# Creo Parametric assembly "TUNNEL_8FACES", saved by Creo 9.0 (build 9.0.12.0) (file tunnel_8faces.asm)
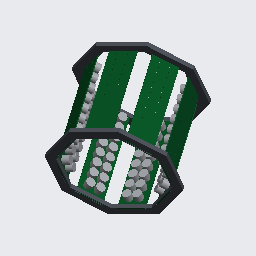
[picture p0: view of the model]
Units: millimeter Newton Second (mmNs); MM, TONNE, SECS

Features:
  1. coordinate system "TUNNEL_8FACES"
  2. imported feature "Import Feature id 4"
  3. component "TUNNEL_8FACES_1"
